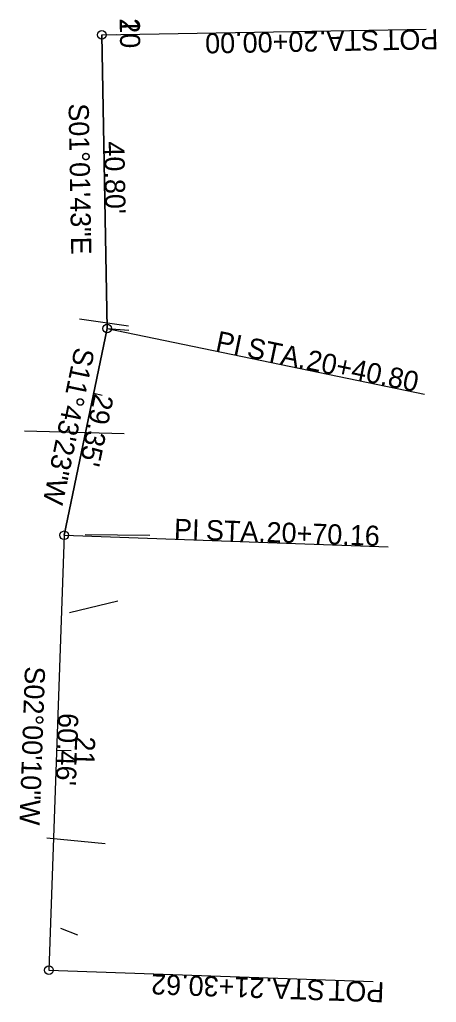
# Model space of a CAD drawing. Extents: x 1392784 to 1392842, y 437928 to 438064.
import ezdxf

# ---------------------------------------------------------------- set-up
doc = ezdxf.new("R2010")
doc.units = 0
for name, color, linetype in [('Default', 7, 'Continuous'), ('LT_X_PullBox', 7, 'Continuous'), ('SG_X_Poles', 7, 'Continuous'), ('SH_Text', 7, 'Continuous'), ('SV_X_Mon_Cells_Found', 7, 'Continuous'), ('UT_X_Gas_Cells', 7, 'Continuous'), ('VG_X_Cells', 7, 'Continuous')]:
    doc.layers.add(name, color=color, linetype=linetype)

msp = doc.modelspace()

# ---------------------------------------------------------------- linework, layer by layer
at = {"layer": 'Default'}
for p, q in [((1392795.91, 438062.02), (1392796.64, 438021.22)), ((1392795.91, 438062.02), (1392796.64, 438021.22)), ((1392795.91, 438062.02), (1392796.64, 438021.22)), ((1392795.91, 438062.02), (1392796.64, 438021.22)), ((1392795.91, 438062.02), (1392796.64, 438021.22)), ((1392796.64, 438021.22), (1392790.68, 437992.48))]:
    msp.add_line(p, q, dxfattribs=at)
at = {"layer": 'SG_X_Poles'}
for p, q in [((1392795.91, 438062.02), (1392797.91, 438062.05)), ((1392795.91, 438062.02), (1392797.91, 438062.05)), ((1392794.77, 438012.21), (1392795.95, 438011.97)), ((1392789.63, 437962.65), (1392791.63, 437962.58))]:
    msp.add_line(p, q, dxfattribs=at)
at = {"layer": 'SH_Text'}
for p, q in [((1392795.91, 438062.02), (1392840.9, 438062.82)), ((1392792.78, 438022.54), (1392799.58, 438021.6)), ((1392796.64, 438021.22), (1392799.64, 438020.96)), ((1392785.18, 438007.01), (1392799.01, 438006.63)), ((1392793.58, 437992.61), (1392802.55, 437992.48)), ((1392791.39, 437981.76), (1392798.14, 437983.36)), ((1392788.26, 437950.46), (1392796.34, 437949.66)), ((1392792.55, 437936.93), (1392790.22, 437937.83)), ((1392788.56, 437932.05), (1392833.54, 437930.48))]:
    msp.add_line(p, q, dxfattribs=at)
for centre in [(1392795.91, 438062.02), (1392788.56, 437932.05)]:
    msp.add_circle(centre, 0.6, dxfattribs=at)
at = {"layer": 'SV_X_Mon_Cells_Found'}
for p, q in [((1392796.64, 438021.22), (1392840.7, 438012.07)), ((1392790.68, 437992.48), (1392835.65, 437990.9))]:
    msp.add_line(p, q, dxfattribs=at)
for centre in [(1392796.64, 438021.22), (1392790.68, 437992.48)]:
    msp.add_circle(centre, 0.6, dxfattribs=at)
at = {"layer": 'UT_X_Gas_Cells'}
for p, q in [((1392795.91, 438062.02), (1392796.64, 438021.22)), ((1392796.64, 438021.22), (1392795.91, 438062.02)), ((1392795.91, 438062.02), (1392796.64, 438021.22)), ((1392795.91, 438062.02), (1392796.64, 438021.22)), ((1392790.68, 437992.48), (1392796.64, 438021.22)), ((1392796.64, 438021.22), (1392790.68, 437992.48)), ((1392796.64, 438021.22), (1392790.68, 437992.48)), ((1392790.68, 437992.48), (1392788.56, 437932.05))]:
    msp.add_line(p, q, dxfattribs=at)

# ---------------------------------------------------------------- texts
at = {"layer": 'LT_X_PullBox'}
for s, rotation, p in [("40.80'", 271.0286, (1392796.22, 438047.18)), ("40.80'", 271.0286, (1392796.22, 438047.18)), ("29.35'", 258.277, (1392794.83, 438012.29)), ("60.46'", 267.9971, (1392789.86, 437967.82))]:
    msp.add_text(s, height=2.8, rotation=rotation, dxfattribs=at).set_placement(p)
at = {"layer": 'SG_X_Poles'}
for s, rotation, p in [('20', 271.0286, (1392798.37, 438064.29)), ('10', 271.0286, (1392798.37, 438064.29)), ('21', 267.9971, (1392792.2, 437964.6))]:
    msp.add_text(s, height=2.8, rotation=rotation, dxfattribs=at).set_placement(p)
at = {"layer": 'SH_Text'}
for s, rotation, p in [('20+00.00', 181.0286, (1392825.93, 438062.51)), (' STA. ', 181.0286, (1392835.38, 438062.68)), ('POT', 181.0286, (1392842.58, 438062.81)), ('21+30.62', 177.9971, (1392818.51, 437930.96)), (' STA. ', 177.9971, (1392827.95, 437930.63)), ('POT', 177.9971, (1392835.15, 437930.38))]:
    msp.add_text(s, height=2.8, rotation=rotation, dxfattribs=at).set_placement(p)
at = {"layer": 'SV_X_Mon_Cells_Found'}
for s, rotation, p in [('PI', 348.277, (1392811.56, 438018.17)), (' STA. ', 348.277, (1392814.88, 438017.48)), ('20+40.80', 348.277, (1392824.13, 438015.56)), ('PI', 357.9971, (1392805.88, 437991.99)), (' STA. ', 357.9971, (1392809.27, 437991.87)), ('20+70.16', 357.9971, (1392818.72, 437991.54))]:
    msp.add_text(s, height=2.8, rotation=rotation, dxfattribs=at).set_placement(p)
at = {"layer": 'VG_X_Cells'}
for s, rotation, p in [('S01°01\'43"E', 271.0286, (1392791.28, 438052.47)), ('S01°01\'43"E', 271.0286, (1392791.28, 438052.47)), ('S11°43\'23"W', 258.277, (1392792.18, 438018.72)), ('S02°00\'10"W', 267.9971, (1392785.24, 437974.31))]:
    msp.add_text(s, height=2.8, rotation=rotation, dxfattribs=at).set_placement(p)

doc.saveas('drawing.dxf')
